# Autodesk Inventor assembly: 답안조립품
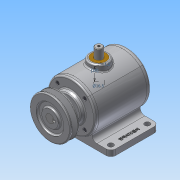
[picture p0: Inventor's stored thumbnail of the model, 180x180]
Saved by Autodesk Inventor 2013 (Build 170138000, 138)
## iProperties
Created: 2015-08
Part Number: 답안조립품
Document SubType Name: Assembly
Designer: Administrator
Mass: 2990.33 g
Surface Area: 2017.36 cm^2
Volume: 938.374 cm^3
Density: 3.18671 g/cm^3
Author: Administrator
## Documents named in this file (14)
- C:\Users\Administrator\Desktop\350806V1039\답안조립품.iam
- C:\Users\Administrator\Desktop\350806V1039\본체.ipt
- C:\Users\Administrator\Desktop\350806V1039\뒷커버.ipt
- C:\Users\Administrator\Desktop\350806V1039\베어링 6203.ipt
- C:\Users\Administrator\Desktop\350806V1039\M4-소켓머리.ipt
- C:\Users\Administrator\Desktop\350806V1039\축.ipt
- C:\Users\Administrator\Desktop\350806V1039\앞커버.ipt
- C:\Users\Administrator\Desktop\350806V1039\오일실.ipt
- C:\Users\Administrator\Desktop\350806V1039\KS B 1311 - 5 x 5 x 18I.ipt
- C:\Users\Administrator\Desktop\350806V1039\V-벨트풀리.ipt
- C:\Users\Administrator\Desktop\350806V1039\KS B 1028  - 납작점M4x5.ipt
- C:\Users\Administrator\Desktop\350806V1039\슬라이더.ipt
- C:\Users\Administrator\Desktop\350806V1039\부시.ipt
- C:\Users\Administrator\Desktop\350806V1039\스프링.ipt
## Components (14 placed, 6 different names)
1. 7-베어링 6203:1
2. 7-베어링 6203:2
3. 8-오일실:1
4. KS B 1311 (I) 5 x 5 x 18:1 — 각도:1, 각도:3
5. V-벨트풀리:1 — 각도:3
6. KS B 1028 납작점 - 미터 납작점M4x5:1
7. 9-M4-소켓머리:1
8. 9-M4-소켓머리:2
9. 9-M4-소켓머리:3
10. 9-M4-소켓머리:4
11. 9-M4-소켓머리:5
12. 9-M4-소켓머리:6
13. 9-M4-소켓머리:7
14. 9-M4-소켓머리:8
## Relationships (2: Angle 2)
- 각도:1 [Angle]: KS B 1311 (I) 5 x 5 x 18:1
- 각도:3 [Angle]: KS B 1311 (I) 5 x 5 x 18:1 ↔ V-벨트풀리:1
